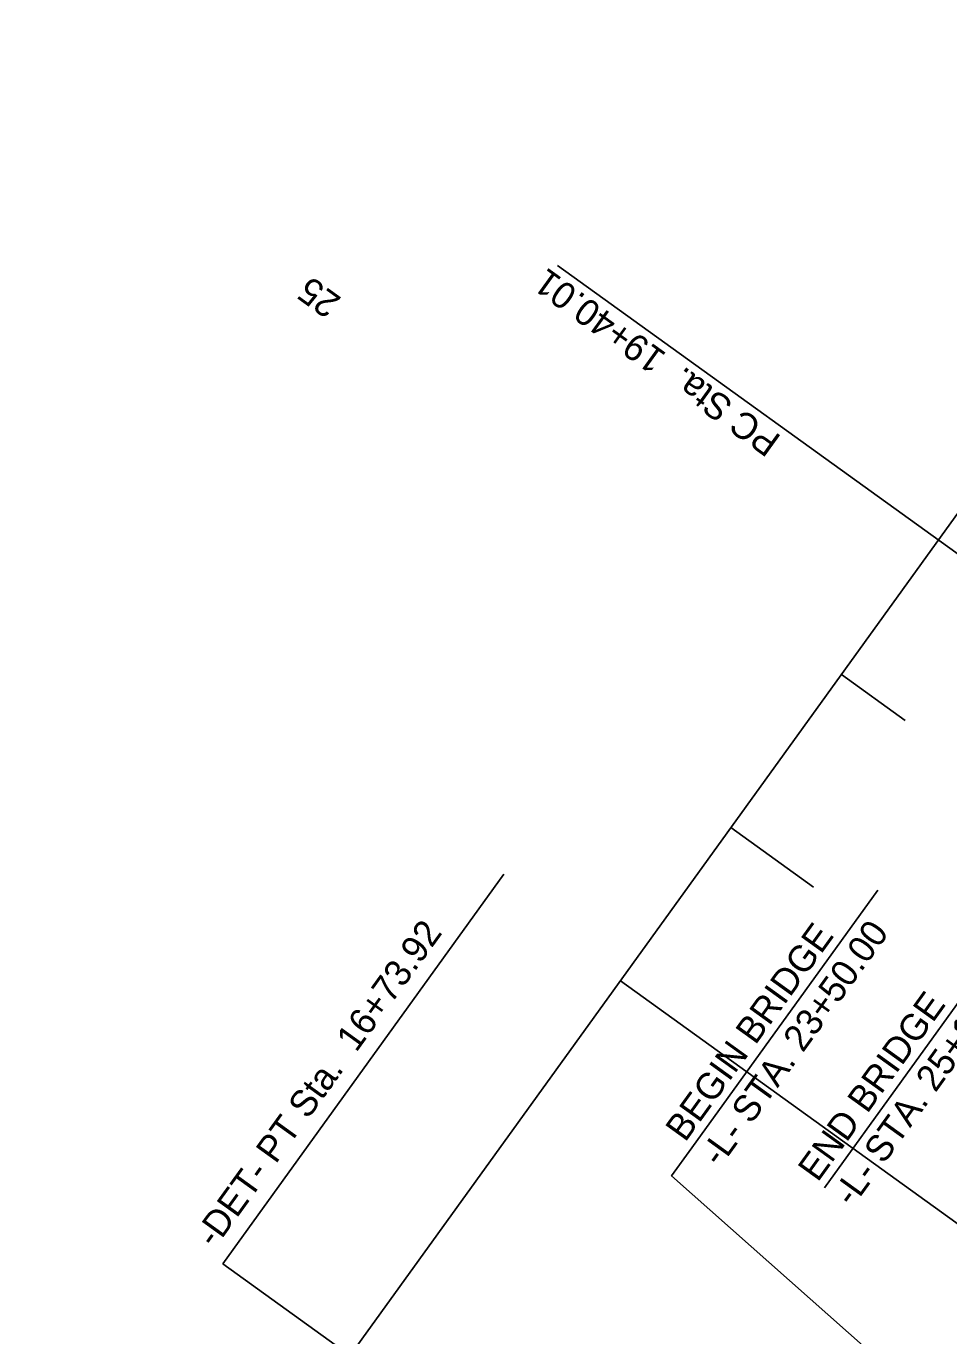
# Model space of a CAD drawing. Extents: x 2189281 to 2191267, y 386656 to 389012.
# Drawn here: x 2190028.9 to 2190273, y 387931.7 to 388278.3 of the extents above; entities that cross this region are included whole.
import ezdxf

# ---------------------------------------------------------------- set-up
doc = ezdxf.new("R2010")
doc.units = 0
for name, color, linetype in [('Prop DSN Text', 7, 'Continuous'), ('Prop Horizontal Alignment Station Label', 7, 'Continuous'), ('Prop Horizontal Alignment Tick Label', 7, 'Continuous'), ('Scratch_Level_5', 7, 'Continuous')]:
    doc.layers.add(name, color=color, linetype=linetype)

msp = doc.modelspace()

# ---------------------------------------------------------------- linework, layer by layer
at = {"layer": 'Prop DSN Text'}
for p, q in [((2190254.17, 388049.61), (2190204.99, 387981.41)), ((2190288.26, 388037.68), (2190240.06, 387970.84))]:
    msp.add_line(p, q, dxfattribs=at)
msp.add_lwpolyline([(2190204.99, 387981.41), (2190199.63, 387973.98), (2190319.03, 387868.07)], dxfattribs=at)
at = {"layer": 'Prop Horizontal Alignment Station Label'}
for p, q in [((2190391.24, 388055.01), (2190169.41, 388214.99)), ((2190155.25, 388053.86), (2190080.89, 387950.75)), ((2190235.59, 387839.18), (2190080.89, 387950.75))]:
    msp.add_line(p, q, dxfattribs=at)
at = {"layer": 'Scratch_Level_5'}
for p, q in [((2189367.15, 386890.09), (2190537.02, 388512.26)), ((2190244.55, 388106.72), (2190261.43, 388094.55)), ((2190215.31, 388066.16), (2190237.13, 388050.43)), ((2190186.06, 388025.61), (2190306.09, 387939.05))]:
    msp.add_line(p, q, dxfattribs=at)

# ---------------------------------------------------------------- texts
at = {"layer": 'Prop DSN Text'}
for s, p in [('BEGIN BRIDGE', (2190203.22, 387982.69)), ('-L- STA. 23+50.00', (2190212.44, 387976.04)), ('-L- STA. 25+10.00', (2190247.51, 387965.47)), ('END BRIDGE', (2190238.28, 387972.12))]:
    msp.add_text(s, height=7, rotation=54.2018, dxfattribs=at).set_placement(p)
at = {"layer": 'Prop Horizontal Alignment Station Label'}
for s, rotation, p in [('PC Sta.  19+40.01', 144.2018, (2190228.94, 388169.59)), ('-DET- PT Sta.  16+73.92', 54.2018, (2190078.75, 387954.59))]:
    msp.add_text(s, height=7, rotation=rotation, dxfattribs=at).set_placement(p)
at = {"layer": 'Prop Horizontal Alignment Tick Label'}
msp.add_text('25', height=7, rotation=144.2018, dxfattribs=at).set_placement((2190112.53, 388206.24))

doc.saveas('drawing.dxf')
